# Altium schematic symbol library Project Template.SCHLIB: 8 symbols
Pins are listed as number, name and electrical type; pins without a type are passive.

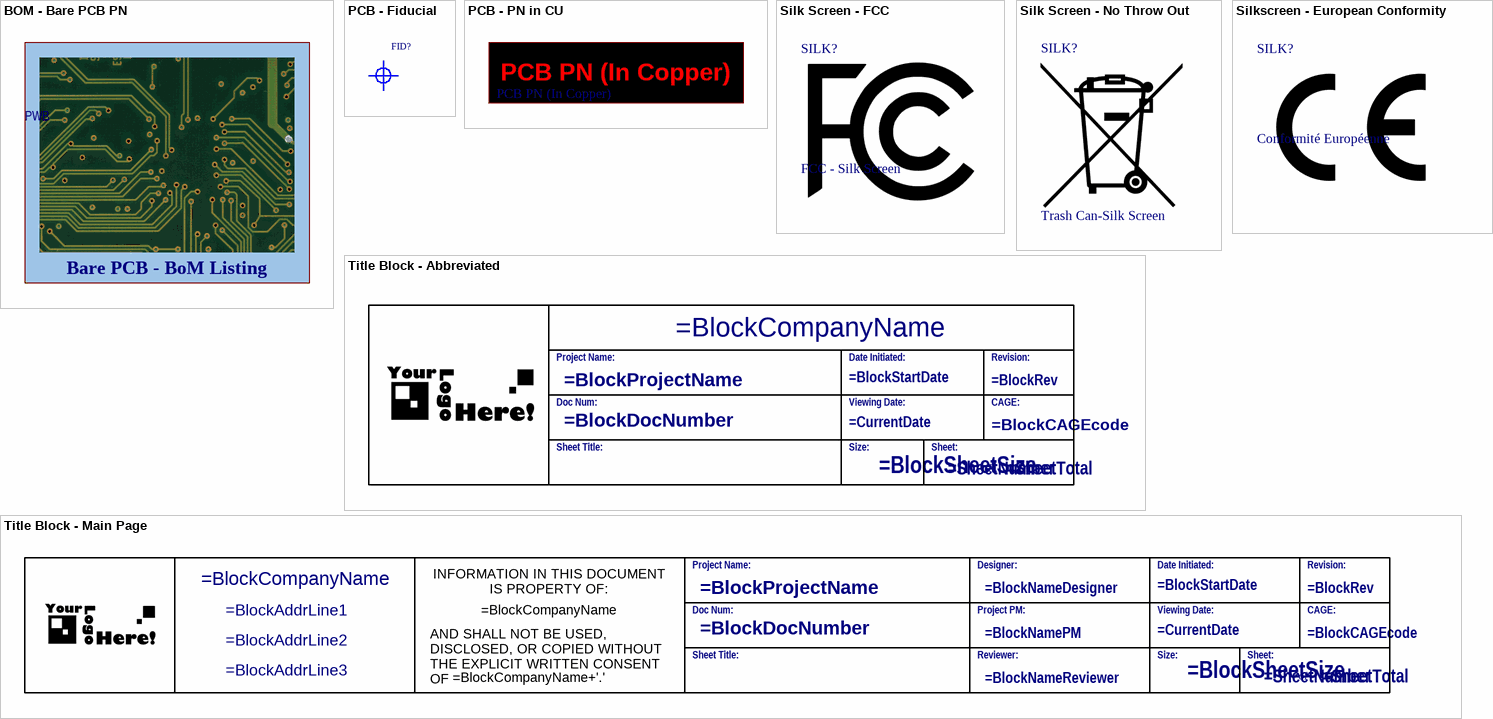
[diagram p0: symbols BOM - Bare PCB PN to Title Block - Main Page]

## BOM - Bare PCB PN
designator FAB?, comment PWB  (mechanical)
Bare PCB Part Number

## PCB - Fiducial
designator FID?, comment Fiducial, 1:3mm  (value not drawn)  (no BOM)
footprint FIDUCIAL 1MM
pins: 1 NC

## PCB - PN in CU
designator PCB PN (In Copper)?, comment PCB PN (In Copper)  (no BOM)
PCB Part Number (In Copper)
footprint PCB PN (In Copper)

## Silk Screen - FCC
designator SILK?, comment FCC - Silk Screen  (no BOM)
footprint LOGO - FCC

## Silk Screen - No Throw Out
designator SILK?, comment Trash Can-Silk Screen  (no BOM)
footprint LOGO - NO THROW

## Silkscreen - European Conformity
designator SILK?, comment Conformité Européenne  (no BOM)
footprint Logo - European Conformity

## Title Block - Abbreviated
designator TitleBlock?  (value not drawn)  (graphical)
Title Block for company.  Textual information is either linked to the parameters listed in the project options or "as is" text

## Title Block - Main Page
designator TitleBlock?  (value not drawn)  (graphical)
Title Block for company.  Textual information is either linked to the parameters listed in the project options or  "as is" text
